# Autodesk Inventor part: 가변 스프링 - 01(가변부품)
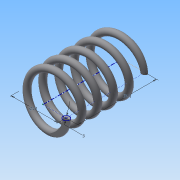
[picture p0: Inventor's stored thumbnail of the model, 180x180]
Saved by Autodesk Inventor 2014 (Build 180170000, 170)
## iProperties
Created: 2015-09
Part Number: 가변 스프링 - 01(가변부품)
Material: 강철, 탄소
Document SubType Name: Modeling
Designer: study
Density: 7.87 g/cm^3
Appearance: 반연마
Mass: 18.9102 g
Surface Area: 32.5696 cm^2
Volume: 2.40281 cm^3
Author: study
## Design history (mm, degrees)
sketch "스케치1"
  geometry: L1 (0, 38.958)-(11, 38.958); L2 (11, 38.958)-(11, 0); L3 (11, 0)-(0, 0); L4 (0, 0)-(0, 38.958); C1 r 1.5 at (11, 0); 1 further point
  constraints: 8 end point, 2 coincident, 2 parallel, 1 centre point, 1 horizontal, 1 perpendicular
  dimensions: "d0" = 3 diameter of C1; "d1" = 22 diameter of L2 L4; "d2" = 38.95829 distance of L1.end L2.end (derived)
feature "코일1" sketch "스케치1" pitch "d3" = 10; turns "d5" = 5; dims "d4" = 38.95829 (= d2), "d6" = 0, angle "d7" = 90 deg, angle "d8" = 90 deg, "d9" = 0, "d10" = 0
sketch "스케치2"
  geometry: L1 (-12.5, 0)-(-9.5, 0) reference; 1 further point
  constraints: 1 horizontal alignment
extrude "돌출1" cut sketch "스케치2" stored distance "d11" = 10; taper "d12" = 0 deg
node "작업 평면1"
sketch "스케치3"
  geometry: L1 (-9.5, 0)-(-12.5, 0) reference; 1 further point
  constraints: 1 horizontal alignment
extrude "돌출2" cut sketch "스케치3" stored distance "d14" = 10; taper "d15" = 0 deg
node "솔리드1"
node "절단 모서리 투영1"
node "절단 모서리 투영2"
other parameters: "d13" = 38.95829 (= d2)
